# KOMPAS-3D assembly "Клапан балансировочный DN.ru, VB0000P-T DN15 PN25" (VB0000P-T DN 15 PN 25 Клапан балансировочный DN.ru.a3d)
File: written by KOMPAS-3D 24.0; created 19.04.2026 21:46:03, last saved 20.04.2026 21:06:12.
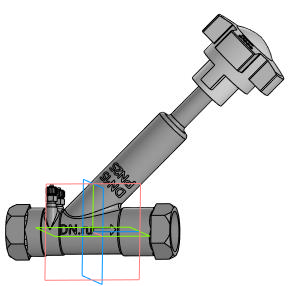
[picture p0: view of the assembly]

Document properties: Автор: mrdid; Полное имя файла: C:\Работа\VB0000P-T DN X PN 25 Клапан балансировочный DN.ru\DN15\исходные материалы\VB0000P-T DN 15 PN 25 Клапан балансировочный DN.ru.a3d

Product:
- Component [detail]: Деталь  | qty 1  | pos. 1  | Масса: 0.310699; Автор: mrdid; source file: VB0000P-T DN 15 PN 25 Клапан балансировочный DN.ru.m3d
- Component [detail]: Деталь2  | qty 1  | pos. 2  | Масса: 0.240364; Автор: tyuri; additional columns: Типовые; source file: Деталь2 - Деталь2.m3d
- Part/product: Клапан балансировочный DN.ru  | designation VB0000P-T DN15 PN25
    Масса: 0.49
    Раздел спецификации: Прочие изделия
    Примечание: D080-01175

Referenced files in C:\Работа\VB0000P-T DN X PN 25 Клапан балансировочный DN.ru\DN15\исходные материалы\: VB0000P-T DN 15 PN 25 Клапан балансировочный DN.ru.m3d, Деталь2 - Деталь2.m3d
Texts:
  VB0000P-T DN15 PN25
  Деталь2 Деталь2
  Плоскость XY.Начало координат
  Плоскость ZY.Начало координат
